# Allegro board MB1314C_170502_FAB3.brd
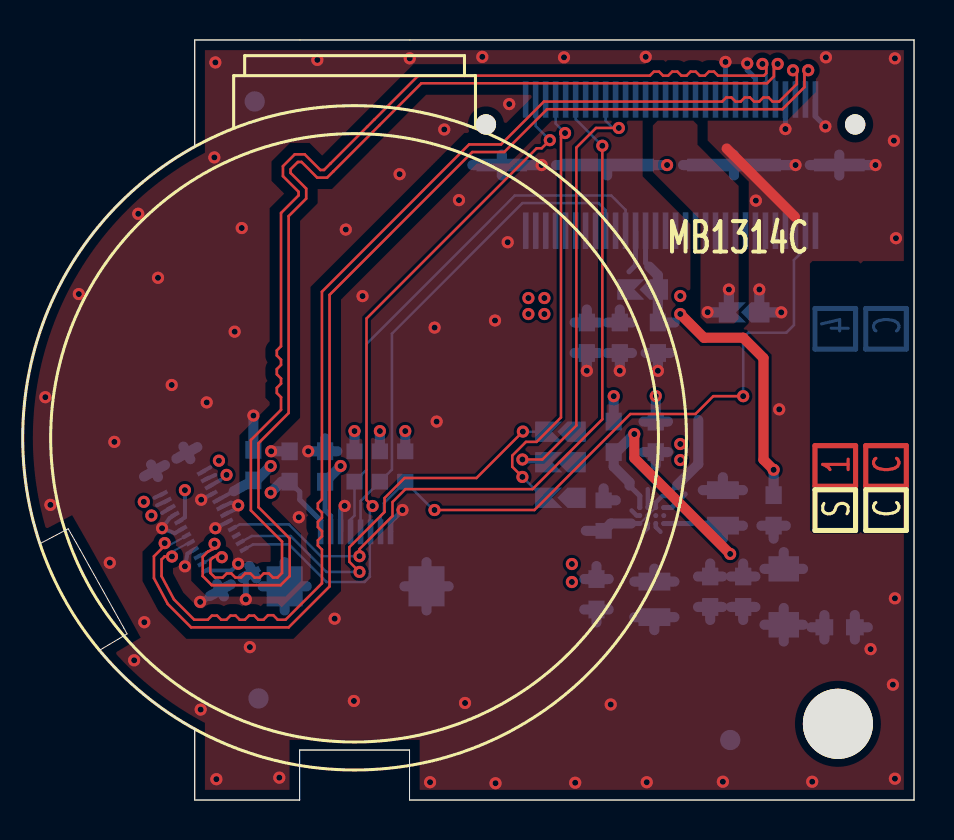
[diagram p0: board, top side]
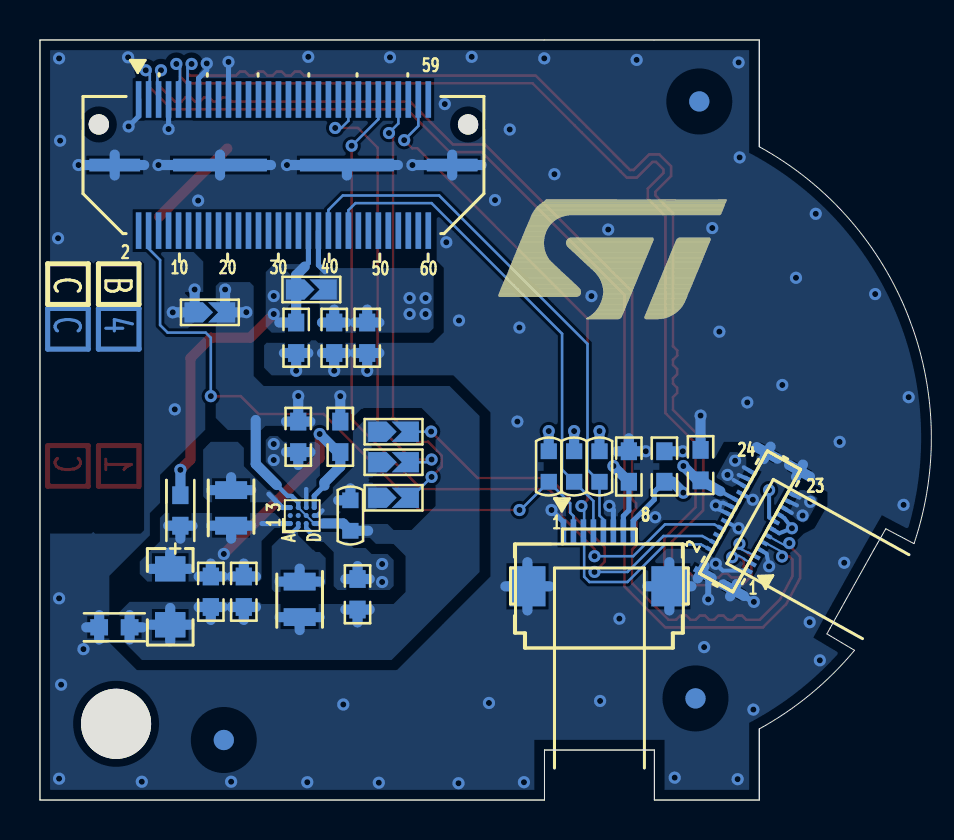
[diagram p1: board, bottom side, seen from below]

Outline 43.75 x 38 mm; copper layers: TOP, L2_GND, L3_VCC, BOTTOM. Coordinates in mm from the lower left corner of the outline.
Outline path: 7.75,32.67 arc(0.27,24.15) 0,12.82 0.02,12.83 1.41,13.56 1.99,12.55 4.21,8.59 4.36,8.31 2.98,7.49 arc(5.18,5.3) 7.75,3.55 ; 7.75,32.67 7.75,38 ; 7.75,32.67 7.75,38 ; 7.75,38 13.01,38 ; 7.75,38 13.01,38 ; 13.01,38 18.51,38 ; 13.01,38 18.51,38 ; 7.75,3.55 7.75,0 ; 7.75,3.55 7.75,0 ; 7.75,0 13,0 ; 7.75,0 13,0 ; 13,0 13,2.5 ; 13,0 13,2.5 ; 13,2.5 18.5,2.5 ; 13,2.5 18.5,2.5 ; 18.5,2.5 18.5,0 ; 18.5,2.5 18.5,0 ; 18.51,38 43.75,38 ; 18.51,38 43.75,38 ; 18.5,0 43.75,0 ; 18.5,0 43.75,0 ; 43.75,0 43.75,38 ; 43.75,0 43.75,38

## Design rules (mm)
net group DIFFPAIR1: nets HSSI_D0_N HSSI_D0_P

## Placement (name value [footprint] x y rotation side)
C1  100nF  [0603C]  30.92 23.11 270 bottom
C2  100nF  [0603C]  29.02 23.11 270 bottom
C3  100nF  [0603C]  27.37 23.11 90 bottom
C4  GRM188R61A106KE69D  [0603C]  30.82 18.16 90 bottom
C5  GRM188R61A106KE69D  [0603C]  28.71 18.16 90 bottom
C6  100nF  [0603C]  10.68 16.75 270 bottom
C7  100nF  [0603C]  14.27 16.68 270 bottom
C8  100nF  [0603C]  12.49 16.68 270 bottom
C9  GRM188R61A106KE69D  [0603C]  33.54 10.41 270 bottom
C10  GRM188R61A106KE69D  [0603C]  27.85 10.29 270 bottom
C11  10uF  [TAN-A]  37.23 10.16 90 bottom
C12  100nF  [0603C]  35.19 10.41 270 bottom
CN1  QTH-030-02-F-D-A-K-TR  [QTH-030-02-F-D-A]  31.56 31.75 180 bottom
CN2  BM20B(0.8)-24DS-0.4V(51)  [HRS_BM20B-24DS-0R4V]  8.19 13.93 119 bottom
CN3  FH19C-8S-05SH  [CONN_8SM_FPC05008-09200]  17.55 13.41 180 bottom
L1  DFE201610E-4R7M=P2  [0806L]  34.18 14.61 270 bottom
L2  DFE201610E-4R7M=P2  [0806L]  30.75 10.03 90 bottom
L3  BEAD(FCM1608KF-601T03)  [0603L]  36.72 14.48 270 bottom
L4  BEAD(FCM1608KF-601T03)  [0603L]  40.02 8.64 180 bottom
NOREF  -  []  175.99 162.03 0 top
NOREF#2  -  []  -3.54 97 0 top
NOREF#3  -  [unnamed#2]  39.94 3.81 0 top
NOREF#4  -  []  7.75 0 0 top
NOREF#5  -  []  369.84 -81.28 0 top
NOREF#6  -  []  43.75 0 90 top
NOREF#7  -  []  -1.25 0 0 top
NOREF#8  -  []  15.75 18.11 0 top
NOREF#9  -  []  7.75 38 0 top
NOREF#10  -  []  165.46 127.75 0 top
NOREF#11  -  []  18.5 0 0 top
NOREF#12  -  []  43.11 16.7 90 top
NOREF#13  -  []  38.81 35.03 0 top
NOREF#14  -  []  43.75 0 90 top
NOREF#15  -  []  0.26 24.12 0 top
NOREF#16  -  []  38.81 35.03 90 top
NOREF#17  -  []  2.81 -24.89 0 top
NOREF#18  -  []  41.29 2.7 0 top
NOREF#19  -  []  39.94 3.81 0 top
NOREF#20  -  []  40.57 16.7 90 top
NOREF#21  Value  []  15.75 18.11 180 top
NOREF#22  -  []  7.75 0 0 top
NOREF#23  -  [unnamed#2]  10.94 5.08 180 bottom
NOREF#24  -  [unnamed#2]  10.75 34.93 180 bottom
NOREF#25  -  [unnamed#2]  34.55 3 180 bottom
R1  4K7  [0603R]  18.28 16.68 270 bottom
R2  [N_A]  [0603R]  17.01 16.68 90 bottom
R3  [N_A]  [0603R]  15.74 16.68 90 bottom
R4  [N_A]  [0603R]  28.21 14.22 90 bottom
SB1  Solder Bridge OFF  [SB_0603]  30.16 25.53 0 bottom
SB2  Solder Bridge OFF  [SB_0603]  35.24 24.38 0 bottom
SB3  Solder Bridge ON  [SB_0603]  26.05 18.41 0 bottom
SB4  Solder Bridge OFF  [SB_0603]  26.05 16.89 0 bottom
SB5  Solder Bridge OFF  [SB_0603]  26.05 15.11 0 bottom
U1  SM3321  [WLCSP12_0R4_1R53X1R74]  30.62 14.22 90 bottom

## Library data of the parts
C1-C10 C12 = 0603C
C11 = TAN-A
CN1 = QTH-030-02-F-D-A
CN2 = HRS_BM20B-24DS-0R4V
CN3 = CONN_8SM_FPC05008-09200
L1 L2 = 0806L
L3 L4 = 0603L
R1-R4 = 0603R
SB1-SB5 = SB_0603
U1 = WLCSP12_0R4_1R53X1R74

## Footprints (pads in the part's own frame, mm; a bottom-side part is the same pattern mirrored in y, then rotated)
0603C
  rect 0.889x0.813 smd: 1(-0.762,0) 2(0.762,0)
0603L
  rect 0.889x0.813 smd: 1(-0.762,0) 2(0.762,0)
0603R
  rect 0.787x0.813 smd: 1(-0.762,0) 2(0.762,0)
0806L
  rect 0.889x1.6 smd: 1(-0.889,0) 2(0.889,0)
CONN_8SM_FPC05008-09200
  rect 0.279x1.245 smd: 1(0,0) 2(0.5,0) 3(1,0) 4(1.5,0) 5(2,0) 6(2.5,0) 7(3,0) 8(3.5,0)
  rect 1.803x2.007 smd: 9(-1.8,-2.725) 10(5.3,-2.725)
HRS_BM20B-24DS-0R4V
  rect 0.203x0.457 smd: 1(-2.2,-1.09) 2(-2.2,1.09) 3(-1.8,-1.09) 4(-1.8,1.09) 5(-1.4,-1.09) 6(-1.4,1.09) 7(-1,-1.09) 8(-1,1.09) 9(-0.6,-1.09) 10(-0.6,1.09) 11(-0.2,-1.09) 12(-0.2,1.09) 13(0.2,-1.09) 14(0.2,1.09) 15(0.6,-1.09) 16(0.6,1.09) 17(1,-1.09) 18(1,1.09) 19(1.4,-1.09) 20(1.4,1.09) 21(1.8,-1.09) 22(1.8,1.09) 23(2.2,-1.09) 24(2.2,1.09)
  rect 0.305x0.787 smd: 25(-3.41,0.925) 26(-3.41,-0.925) 27(3.41,0.925) 28(3.41,-0.925)
QTH-030-02-F-D-A
  round 1.016 hole 1.016 unplated: (-9.24,2.03) (9.24,2.03)
  rect 0.279x1.829 smd: 1(-7.25,3.28) 2(-7.25,-3.28) 3(-6.75,3.28) 4(-6.75,-3.28) 5(-6.25,3.28) 6(-6.25,-3.28) 7(-5.75,3.28) 8(-5.75,-3.28) 9(-5.25,3.28) 10(-5.25,-3.28) 11(-4.75,3.28) 12(-4.75,-3.28) 13(-4.25,3.28) 14(-4.25,-3.28) 15(-3.75,3.28) 16(-3.75,-3.28) 17(-3.25,3.28) 18(-3.25,-3.28) 19(-2.75,3.28) 20(-2.75,-3.28) 21(-2.25,3.28) 22(-2.25,-3.28) 23(-1.75,3.28) 24(-1.75,-3.28) 25(-1.25,3.28) 26(-1.25,-3.28) 27(-0.75,3.28) 28(-0.75,-3.28) 29(-0.25,3.28) 30(-0.25,-3.28) 31(0.25,3.28) 32(0.25,-3.28) 33(0.75,3.28) 34(0.75,-3.28) 35(1.25,3.28) 36(1.25,-3.28) 37(1.75,3.28) 38(1.75,-3.28) 39(2.25,3.28) 40(2.25,-3.28) 41(2.75,3.28) 42(2.75,-3.28) 43(3.25,3.28) 44(3.25,-3.28) 45(3.75,3.28) 46(3.75,-3.28) 47(4.25,3.28) 48(4.25,-3.28) 49(4.75,3.28) 50(4.75,-3.28) 51(5.25,3.28) 52(5.25,-3.28) 53(5.75,3.28) 54(5.75,-3.28) 55(6.25,3.28) 56(6.25,-3.28) 57(6.75,3.28) 58(6.75,-3.28) 59(7.25,3.28) 60(7.25,-3.28)
  rect 2.54x0.635 smd: 61(-8.445,0) 64(8.445,0)
  rect 4.699x0.635 smd: 62(-3.175,0) 63(3.175,0)
SB_0603
  round 0.152 smd: 1(-0.762,0) 2(0.762,0)
TAN-A
  rect 1.27x1.524 smd: 1(1.397,0) 2(-1.397,0)
unnamed#2
  round 3.505 hole 3.505 unplated: (0,0)
WLCSP12_0R4_1R53X1R74
  round 0.254 smd: A1(-0.4,0.6) A2(0,0.6) A3(0.4,0.6) B1(-0.4,0.2) B2(0,0.2) B3(0.4,0.2) C1(-0.4,-0.2) C2(0,-0.2) C3(0.4,-0.2) D1(-0.4,-0.6) D2(0,-0.6) D3(0.4,-0.6)

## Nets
+3V3: C1.1 C6.2 C8.2 CN1.36 CN2.16 CN3.8 L3.1 SB1.2
GND: C1.2 C2.2 C3.1 C6.1 C7.1 C8.1 CN1.1 CN1.7 CN1.13 CN1.19 CN1.61 CN1.62 CN1.63 CN1.64 CN2.1 CN2.7 CN2.10 CN2.12 CN2.13 CN2.14 CN2.17 CN2.18 CN2.25 CN2.26 CN2.27 CN2.28 CN3.1 CN3.6 CN3.9 CN3.10 L4.1 SB2.2
VDD: C2.1 C3.2 C7.2 CN1.38 CN2.15 CN3.7 R1.1 R2.2 R3.2 SB1.1
BLGND: C4.2 C5.2 C9.2 C10.2 C11.2 C12.2 L2.1 L4.2 R4.1 SB2.1 U1.B3 U1.C2 U1.D1
DSI_BL_CTRL: CN1.53 SB5.1
DSI_INT: CN1.4 CN3.2 R1.2
DSI_RST: CN1.57 CN2.2 CN3.3
DSI_TE: CN1.49 CN2.8
ELVDD: C4.1 CN2.20 CN2.22 CN2.24 U1.C3
ELVSS: C10.1 CN2.19 CN2.21 CN2.23 U1.C1
HSSI_CLK_N: CN1.5 CN2.9
HSSI_CLK_P: CN1.3 CN2.11
HSSI_D0_N: CN1.11 CN2.3
HSSI_D0_P: CN1.9 CN2.5
I2C_SCL: CN1.44 CN3.4 R2.1
I2C_SDA: CN1.40 CN3.5 R3.1
NETC5_1: C5.1 C9.1 C11.1 C12.1 L1.2 L3.2 U1.A1 U1.D3
NETL1_1: L1.1 U1.A3
NETL2_2: L2.2 U1.B1
NETR4_2: R4.2 SB3.2 SB4.2 SB5.2 U1.D2
SWIRE: CN2.4 SB3.1
SWIRE_MCU: CN1.43 SB4.1

Pads without a net: CN1 2 6 8 10 12 14 15 16 17 18 20 21 22 23 24 25 26 27 28 29 30 31 32 33 34 35 37 39 41 42 45 46 47 48 50 51 52 54 55 56 58 59 60; CN2 6; U1 A2 B2

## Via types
v1: diameter 0.61, hole 0.305, TOP to BOTTOM, 129 vias

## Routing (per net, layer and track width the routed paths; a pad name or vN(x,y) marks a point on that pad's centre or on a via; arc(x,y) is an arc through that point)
+3V3: length 25.4
  TOP w0.508: v1(32.05,24.3) 33.23,23.11 35.19,23.11 36.21,22.1 36.21,17.02 v1(36.72,16.51)
  BOTTOM w0.2: CN2.16 9.7,15.44
  BOTTOM w0.254: CN3.8 14.05,13.97 13,15.02 13,15.41 C8.2 ; CN1.36 30.31,26.86 30.5,26.67
  BOTTOM w0.508: v1(11.55,15.37) 12.09,15.91 C8.2 ; 30.5,26.67 30.92,26.24 SB1.2 C1.1 31.77,23.88 ; v1(11.55,16.7) 10.83,15.98 C6.2 9.7,15.44 ; L3.1 v1(36.72,16.51)
  vias: v1(32.05,25.2)
GND: length 78.3
  TOP w0.508: 37.79,29.16 34.37,32.58
  BOTTOM w0.2: v1(7.25,11.68) 7.38,12.32 CN2.7 ; CN2.12 9.87,14.58 v1(9.92,14.73) 9.84,14.82 9.56,14.87 CN2.14 ; CN2.10 v1(8.78,13.59) ; CN2.18 v1(8.07,15.01) ; CN2.17 6.49,14.1 v1(6.11,13.59) 6.75,13.34 CN2.13 ; v1(9.92,11.81) 9.58,11.47 CN2.1
  BOTTOM w0.254: CN1.13 35.81,36.09 35.4,36.5 v1(35.4,36.83) ; CN3.6 15.05,14.5 15.26,14.71 v1(15.25,14.71) ; v1(18.15,14.5) 17.55,13.9 17.55,13.41 CN3.1 ; CN1.1 38.81,34.18 v1(39.31,33.68) ; CN1.7 v1(37.31,33.55) ; CN1.19 v1(34.31,36.91)
  BOTTOM w0.3: v1(10.3,10.03) 10.3,11.04 CN2.25 ; 9.03,10.49 v1(8.02,9.91)
  BOTTOM w0.508: 25.83,31.75 CN1.63 ; CN1.63 v1(31.39,31.75) ; CN1.63 28.38,31.23 ; CN1.62 v1(37.82,31.75) ; CN1.62 34.73,31.23 ; CN1.62 32.18,31.75 ; CN1.62 34.73,32.27 ; CN3.9 20.45,10.69 ; CN3.9 18.24,10.69 ; CN3.9 19.35,11.89 ; CN3.9 19.35,9.48 ; L4.1 40.78,9.25 ; L4.1 41.43,8.64 ; L4.1 40.78,8.03 ; 38.53,31.75 CN1.61 ; CN1.61 40,31.23 ; CN1.61 v1(41.82,31.75) ; CN1.61 40,32.27 ; CN2.28 5.91,16.15 ; CN2.28 6.26,16.75 ; CN2.28 5.56,16.77 ; CN2.28 5.21,16.17 ; CN3.10 12.25,11.89 ; CN3.10 12.25,9.48 ; CN3.10 13.35,10.69 ; CN3.10 11.14,10.69 ; 28.41,22.35 C2.2 ; C2.2 v1(29.02,21.46) ; C2.2 29.63,22.35 ; 8.51,10.21 9.03,10.49 ; 9.03,10.49 8.86,10.81 ; 9.03,10.49 9.56,10.78 ; 9.03,10.49 9.21,10.18 ; C7.1 14.88,17.44 ; C7.1 v1(13.43,17.44) ; C7.1 14.27,18.09 ; 10.13,11.1 CN2.25 ; CN2.25 10.83,11.08 ; CN2.25 10.48,11.7 ; C1.2 v1(30.92,21.46) ; C1.2 31.53,22.35 ; C1.2 30.31,22.35 ; 6.83,17.07 CN2.27 ; CN2.27 7.87,17.65 ; CN2.27 7.52,17.05 ; CN2.27 7.18,17.67 ; C3.1 v1(27.37,21.46) ; C3.1 26.76,22.35 ; C3.1 27.98,22.35 ; v1(36,25.53) SB2.2 v1(37.1,24.38) ; C8.1 v1(11.57,17.44) ; C6.1 v1(10.68,19.22) ; 23.11,31.23 CN1.64 ; CN1.64 23.11,32.27 ; CN1.64 v1(25.11,31.75) ; CN1.64 21.64,31.75
  vias: v1(0.27,20.14) v1(0.52,14.76) v1(1.95,25.3) v1(3.5,11.86) v1(3.72,17.91) v1(4.71,6.99) v1(4.92,29.31) v1(5.22,8.89) v1(5.91,26.11) v1(6.59,20.75) v1(8.04,4.52) v1(8.35,19.88) v1(8.78,36.88) v1(8.73,32.13) v1(8.83,1.04) v1(9.74,23.42) v1(10.1,28.6) v1(10.51,7.65) v1(11.98,1.12) v1(12.96,14.14) v1(13.88,37.01) v1(14.75,9.07) v1(15.31,28.52) v1(15.71,4.95) v1(16.14,25.2) v1(18,31.29) v1(18.51,37.08) v1(19.52,0.89) v1(19.75,23.62) v1(19.85,18.92) v1(20.23,33.53) v1(20.97,30) v1(21.28,4.85) v1(22.14,37.16) v1(22.77,23.98) v1(22.8,0.84) v1(23.49,34.8) v1(23.41,27.89) v1(26.23,37.13) v1(26.79,0.86) v1(28.57,4.78) v1(30.32,37.16) v1(30.37,0.89) v1(34.18,0.91) v1(35.83,29.97) v1(37,19.53) v1(38.65,0.91) v1(39.33,37.13) v1(41.57,7.54) v1(42.69,5.77) v1(42.79,37.08) v1(42.74,32.97) v1(42.79,10.08) v1(42.79,1.07) v1(42.84,28.09)
VDD: length 14.4
  BOTTOM w0.2: CN2.15 7.25,14.14 v1(7.25,15.49)
  BOTTOM w0.254: CN1.38 29.81,26.75 29.48,26.42 ; C7.2 14.27,14.48 14.55,14.2 CN3.7
  BOTTOM w0.508: C2.1 29.02,24.52 ; C2.1 28.41,23.88 ; C2.1 29.63,23.88 ; C3.2 27.98,23.88 ; C3.2 27.37,24.52 ; C3.2 26.76,23.88 ; R2.2 v1(17.01,18.45) ; R1.1 v1(18.28,18.45) ; R3.2 v1(15.74,18.45) ; v1(15.05,16.7) 15.05,16.69 C7.2
  vias: v1(24.45,25.1) v1(24.45,24.3) v1(25.25,25.1) v1(25.25,24.3)
BLGND: length 29.1
  BOTTOM w0.102: U1.B3 U1.C2 U1.D1
  BOTTOM w0.22: 31.9,15.75 31.35,15.2 31.15,15.2 30.82,14.87 U1.B3
  BOTTOM w0.254: 29.58,13.83 29.9,13.83 29.89,13.82 U1.D1
  BOTTOM w0.508: C10.2 28.46,9.53 ; C10.2 27.24,9.53 ; C10.2 27.85,8.88 ; 38.61,8.64 L4.2 ; L4.2 39.26,9.25 ; L4.2 39.26,8.03 ; 34.58,9.65 C12.2 ; C12.2 35.19,9 ; C12.2 35.8,9.65 ; 29.75,9.14 L2.1 ; L2.1 31.75,9.14 ; L2.1 30.75,8.5 ; C11.2 38.19,8.76 ; C11.2 36.26,8.76 ; C11.2 37.23,9.6 ; C11.2 37.23,7.92 ; C9.2 34.15,9.65 ; C9.2 33.54,9 ; C9.2 32.93,9.65 ; v1(34.48,25.53) SB2.1 33.42,24.38 v1(33.42,24.39) ; 27.32,13.46 R4.1 28.57,13.83 29.58,13.83 ; C5.2 v1(28.71,20.19) ; 32.95,19 32.95,16.8 31.9,15.75 ; 30.21,18.92 C4.2 ; C4.2 v1(30.82,20.2) ; C4.2 31.43,18.92
DSI_BL_CTRL: length 22.3
  TOP w0.127: v1(24.15,16.15) 23.64,16.66 23.64,17.22 24.32,17.91 24.85,17.91 26.08,19.13 26.08,33.15 v1(26.28,33.35)
  BOTTOM w0.127: CN1.53 25.81,33.83 26.28,33.36 v1(26.28,33.35) ; v1(24.15,16.15) 25.19,15.11 SB5.1
DSI_INT: length 33.6
  TOP w0.127: v1(19.75,14.5) 24.75,14.5 29.55,19.3 32.8,19.3 33.7,20.19 v1(35.19,20.19)
  BOTTOM w0.127: v1(35.19,20.19) 35.19,23.11 35.45,23.37 37.35,23.37 37.73,23.75 37.73,27 38.31,27.58 CN1.4 ; v1(19.75,14.5) 19.7,14.5 R1.2 17.21,14.84 17.21,14.36 17.05,14.2 CN3.2
DSI_RST: length 35.6
  TOP w0.127: v1(25.52,32.99) 25.11,32.59 24.86,32.59 16.34,24.08 16.34,15 v1(16.65,14.7)
  BOTTOM w0.127: v1(25.52,32.99) 24.81,33.7 CN1.57 ; CN2.2 10.67,12.78 12.47,12.78 14.35,10.9 16.25,10.9 16.51,11.16 16.51,13.45 ; v1(16.65,14.7) 16.51,14.56 16.51,13.45 ; 16.51,13.45 CN3.3
DSI_TE: length 39.2
  TOP w0.127: v1(28.15,32.72) 28.15,19.04 24.65,15.54 18.29,15.54 17.65,14.9 17.65,14.2 15.99,12.55 v1(15.99,12.19)
  BOTTOM w0.127: v1(28.15,32.72) 28.09,32.77 28.08,32.77 26.81,34.04 CN1.49 ; v1(15.99,12.19) 14.05,12.19 12.46,13.78 10,13.78 CN2.8
ELVDD: length 4.5
  BOTTOM w0.2: CN2.20 9.03,16 ; CN2.22 8.78,16.26 ; CN2.24 8.52,16.64
  BOTTOM w0.22: 30.42,15.55 U1.C3
  BOTTOM w0.508: 30.21,17.4 C4.1 ; C4.1 31.43,17.4 ; C4.1 30.82,16.75
  vias: v1(8.96,16.97) v1(9.34,16.26) v1(32.05,17.8) v1(32.05,17)
ELVSS: length 3.9
  BOTTOM w0.2: CN2.19 6.11,14.35 ; CN2.21 5.86,14.73 ; CN2.23 5.73,15.11
  BOTTOM w0.22: 30.25,13.4 30.25,13.43 30.42,13.6 U1.C1
  BOTTOM w0.508: 27.85,11.05 28.46,11.05 ; 27.85,11.05 27.24,11.05 ; 27.85,11.05 27.85,11.7
  vias: v1(5.2,14.91) v1(5.58,14.22) v1(26.62,11.8) v1(26.62,10.9)
HSSI_CLK_N: length 59.2
  TOP w0.13: v1(37.69,36.49) 37.88,36.3 37.88,35.8 37,34.92 36.67,34.92 36.46,35.13 36.2,35.13 36,34.92 35.74,34.92 35.53,35.13 35.27,35.13 35.07,34.92 34.81,34.92 34.6,35.13 34.35,35.13 34.14,34.92 25.22,34.92 23.08,32.78 21.48,32.78 14.11,25.42 14.11,15.03 13.91,14.83 13.91,14.57 14.11,14.37 14.11,14.11 13.91,13.91 13.91,13.65 14.11,13.45 14.11,13.19 13.91,12.98 13.91,12.72 14.11,12.52 14.11,10.84 12.29,9.01 11.9,9.01 11.68,9.24 11.41,9.24 11.19,9.01 10.93,9.01 10.72,9.22 10.46,9.22 10.26,9.01 10,9.01 9.79,9.22 9.53,9.22 9.33,9.01 9.07,9.01 8.86,9.22 8.61,9.22 8.4,9.01 7.72,9.01 6.71,10.03 6.09,11.19 6.09,12.03 6.24,12.18 v1(6.61,12.18)
  BOTTOM w0.102: CN2.9 7.29,12.78 6.69,12.45 v1(6.61,12.18)
  BOTTOM w0.13: v1(37.69,36.49) 37.87,36.31 37.87,35.92 37.81,35.86 CN1.5
HSSI_CLK_P: length 59.2
  TOP w0.13: v1(6.24,12.85) 6.19,12.67 5.71,12.18 5.71,11.09 6.4,9.8 7.56,8.63 12.45,8.63 14.49,10.68 14.49,25.26 21.64,32.4 23.24,32.4 25.38,34.54 37.16,34.54 38.26,35.64 38.26,36.3 v1(38.45,36.49)
  BOTTOM w0.102: v1(6.24,12.85) 6.25,12.82 6.5,12.75 6.93,12.99 CN2.11
  BOTTOM w0.13: v1(38.45,36.49) 38.25,36.29 38.25,35.94 38.31,35.88 CN1.3
HSSI_D0_N: length 59.4
  TOP w0.13: v1(9.1,12.14) 8.84,12.22 8.64,12.11 8.53,11.99 8.53,11.35 8.76,11.12 9.14,11.12 9.34,11.33 9.57,11.33 9.78,11.12 10.07,11.12 10.27,11.33 10.53,11.33 10.73,11.12 10.99,11.12 11.2,11.33 11.46,11.33 11.66,11.12 11.89,11.12 12.11,11.35 12.11,12.92 10.56,14.48 10.56,18 12.06,19.51 12.06,20.14 11.86,20.35 11.86,20.61 12.06,20.82 12.06,21.08 11.86,21.29 11.86,21.55 12.06,21.75 12.06,22.01 11.86,22.22 11.86,22.48 12.06,22.69 12.06,29.35 12.94,30.23 12.94,30.41 12.16,31.2 12.16,31.7 12.75,32.28 13.25,32.28 14.03,31.5 14.22,31.5 14.53,31.81 16.37,33.66 16.73,34.02 18.93,36.22 30.53,36.22 30.73,36.42 30.98,36.42 31.18,36.22 31.44,36.22 31.64,36.42 31.9,36.42 32.1,36.22 32.36,36.22 32.56,36.42 32.82,36.42 33.02,36.22 33.28,36.22 33.48,36.42 33.74,36.42 33.94,36.22 36.23,36.22 36.35,36.34 36.35,36.61 v1(36.16,36.81)
  BOTTOM w0.102: CN2.3 8.49,12.03 8.5,12.06 8.78,12.22 v1(9.1,12.14)
  BOTTOM w0.13: v1(36.16,36.81) 36.36,36.6 36.36,35.96 36.31,35.91 CN1.11
HSSI_D0_P: length 59.4
  TOP w0.13: v1(36.92,36.81) 36.73,36.61 36.73,36.18 36.39,35.84 19.09,35.84 17,33.75 16.64,33.39 14.68,31.43 14.37,31.12 13.87,31.12 13.09,31.9 12.91,31.9 12.54,31.54 12.54,31.35 13.32,30.57 13.32,30.07 12.45,29.19 12.45,19.35 10.94,17.84 10.94,14.64 12.5,13.08 12.5,11.19 12.04,10.74 8.6,10.74 8.15,11.2 8.15,12.16 8.4,12.42 8.41,12.42 8.66,12.55 v1(8.74,12.81)
  BOTTOM w0.102: v1(8.74,12.81) 8.66,12.56 8.61,12.53 8.33,12.37 8.3,12.38 7.92,12.17
  BOTTOM w0.13: v1(36.92,36.81) 36.74,36.62 36.74,35.96 36.81,35.89 CN1.9
I2C_SCL: length 25.1
  BOTTOM w0.127: CN3.4 16.05,14.95 R2.1 17.61,16.52 17.61,23.31 24.15,29.84 27.96,29.84 28.31,29.49 CN1.44
I2C_SDA: length 27.1
  BOTTOM w0.127: CN1.40 29.31,29.51 28.59,30.23 23.76,30.23 16.34,22.81 16.34,16.52 R3.1 15.74,14.22 15.55,14.03 CN3.5
NETC5_1: length 25.1
  TOP w0.508: v1(34.54,12.3) 29.75,17.1 v1(29.75,18.3)
  BOTTOM w0.254: U1.A1 32.64,13.82 ; U1.D3 30.02,15.21 29.51,15.72
  BOTTOM w0.508: C9.1 33.54,11.82 ; C9.1 34.15,11.18 ; C9.1 32.93,11.18 ; 36.11,13.72 L3.2 ; L3.2 36.72,13.07 ; L3.2 37.33,13.72 ; C11.1 37.23,12.4 ; C11.1 36.26,11.56 ; C11.1 38.19,11.56 ; C12.1 35.19,11.82 ; C12.1 34.58,11.18 ; C12.1 35.8,11.18 ; 34.18,13.07 L1.2 ; L1.2 33.17,13.72 ; L1.2 35.18,13.72 ; v1(29.75,18.3) 28.84,17.4 C5.1 28.71,16.67 29.51,15.88 29.51,15.72
NETL1_1: length 4
  BOTTOM w0.254: U1.A3 31.62,14.62 32.29,15.3
  BOTTOM w0.508: L1.1 34.18,16.14 ; L1.1 35.18,15.49 ; L1.1 33.17,15.49
NETL2_2: length 3.2
  BOTTOM w0.22: U1.B1 30.82,13.65 31.06,13.41
  BOTTOM w0.508: L2.2 31.75,10.92 ; L2.2 30.75,11.57 ; L2.2 29.75,10.92
NETR4_2: length 1.7
  BOTTOM w0.22: 29.61,14.48 29.86,14.22 U1.D2
  BOTTOM w0.508: 28.82,14.99 R4.2 28.21,15.58
SWIRE: length 20.9
  TOP w0.127: v1(15.99,11.4) 15.48,11.91 15.48,12.64 17.25,14.4 17.25,15.1 18.25,16.1 21.85,16.1 v1(24.17,18.42)
  BOTTOM w0.127: v1(15.99,11.4) 14.34,11.4 12.55,13.2 10.6,13.2 CN2.4 ; v1(24.17,18.42) 24.18,18.41 SB3.1
SWIRE_MCU: length 22.9
  TOP w0.127: v1(28.97,33.6) 27.83,33.6 26.85,32.62 26.85,18.73 25.14,17.03 v1(24.15,17.03)
  BOTTOM w0.127: SB4.1 24.28,16.89 v1(24.15,17.03) ; CN1.43 28.31,33.96 28.67,33.6 v1(28.97,33.6)

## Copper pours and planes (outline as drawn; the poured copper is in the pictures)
+3V3 on BOTTOM (solid shape): 31.43,25.02 30.51,25.02 30,25.53 30.51,26.04 31.43,26.04
+3V3 on BOTTOM: 30.55,26.8 32.05,26.8 32.45,26.4 32.45,23.67 32.15,23.37 30.5,23.37 30.35,23.52 30.35,26.6
+3V3 on L3_VCC: 13.55,13.75 12.95,14.35 12.23,14.35 11,15.58 11,17.69 11.35,18.05 13.74,18.05 14.09,17.69 14.09,16.29 14.64,15.75 18.75,15.75 25.86,22.86 29.86,22.86 30.5,23.5 30.5,26.42 30.88,26.8 32.29,26.8 32.49,26.59 32.49,19.25 29.24,19.25 23.74,13.75
GND on BOTTOM (solid shape): 36.51,23.88 35.59,23.88 35.08,24.38 35.59,24.89 36.51,24.89
GND on TOP: 8.25,0.51 8.25,3.86 5.85,5.41 3.76,7.36 5.04,8.12 4.65,8.83 2.43,12.8 1.61,14.24 0.3,13.55 0.91,24.38 8.25,32.36 8.25,37.49 43.24,37.49 43.24,0.51 19,0.51 19,3.01 12.49,3.01 12.49,0.51 ; 1 cut-out
GND on BOTTOM: 8.25,0.51 8.25,3.86 5.85,5.41 3.76,7.36 5.04,8.12 4.65,8.83 2.43,12.8 1.61,14.24 0.3,13.55 0.91,24.38 8.25,32.36 8.25,37.49 43.24,37.49 43.24,0.51 19,0.51 19,3.01 12.49,3.01 12.49,0.51 ; 4 cut-outs
GND on L2_GND: 8.25,0.51 8.25,3.86 5.85,5.41 3.76,7.36 5.04,8.12 4.65,8.83 2.43,12.8 1.61,14.24 0.3,13.55 0.91,24.38 8.25,32.36 8.25,37.49 43.24,37.49 43.24,0.51 19,0.51 19,3.01 12.49,3.01 12.49,0.51
VDD on BOTTOM (solid shape): 29.75,25.52 30.25,25.02 28.89,25.02 28.89,26.04 30.26,26.04
VDD on BOTTOM: 29.61,23.37 24.27,23.37 24.05,23.59 24.05,26.4 24.25,26.6 29.55,26.6 29.75,26.4 29.75,23.51
VDD on L3_VCC: 32.7,0.51 32.7,15.59 33.4,16.29 33.4,18.71 33,19.11 33,26.81 32.5,27.3 30.62,27.3 29.99,26.67 29.99,23.75 29.61,23.37 25.65,23.37 18.54,16.25 14.85,16.25 14.6,16.51 14.6,17.91 13.95,18.55 11.14,18.55 10.74,18.15 8.54,18.15 7.79,17.41 7.79,15.05 6.75,15.05 5.35,16.45 -0.27,16.45 1.55,25.71 8.25,32.36 8.25,37.49 43.24,37.49 43.24,0.51
BLGND on BOTTOM (solid shape): 34.83,24.38 35.33,23.88 33.97,23.88 33.97,24.89 35.34,24.89
BLGND on TOP: 30.95,34.01 32.65,34.01 32.91,33.76 32.91,32.77 34.97,30.71 34.97,24.05 34.74,23.83 33.37,23.83 33.06,24.13 33.06,29.01 30.67,31.39 30.67,33.73
BLGND on BOTTOM: 33.25,25.9 34.75,25.9 34.95,25.7 34.95,19.1 34.35,18.5 28.05,18.5 27.85,18.7 27.85,19.3 27.55,19.6 24.65,19.6 23.95,18.9 23.95,14.7 25.15,13.5 26.05,13.5 26.35,13.8 27.95,13.8 28.15,13.6 28.15,13 27.95,12.8 26.05,12.8 25.45,12.2 25.45,10.4 26.05,9.8 32.65,9.8 32.76,9.91 39.26,9.91 39.77,9.4 39.77,8.13 38.64,7 26.15,7 21.75,11.4 21.75,19.2 23.25,20.7 32.55,20.7 33.05,21.2 33.05,25.7
DSI_BL_CTRL on BOTTOM (solid shape): 25.64,15.11 26.14,14.61 24.78,14.61 24.78,15.62 26.15,15.62
ELVDD on BOTTOM: 29.73,17.91 31.55,17.91 31.85,18.2 32.25,18.2 32.45,18 32.45,16.91 30.64,15.1 30.45,15.1 30.24,15.3 30.24,15.37 29.73,15.88
ELVDD on BOTTOM: 9.64,15.99 9.42,15.79 9.1,15.65 8.91,15.75 8.4,16.64 8.4,17.12 8.86,17.4 9.22,17.4 9.92,16.13
ELVDD on L3_VCC: 11.35,10.25 10.45,11.15 8.3,14.97 8.3,17.19 8.75,17.65 10.49,17.65 10.49,15.38 12.03,13.85 12.74,13.85 13.34,13.25 23.95,13.25 29.45,18.75 32.64,18.75 32.89,18.49 32.89,16.51 32.34,15.95 29.44,15.95 23.74,10.25
ELVSS on BOTTOM: 28.85,10.5 26.25,10.5 26.05,10.7 26.05,12 26.35,12.3 27.15,12.3 27.45,12.6 28.05,12.6 28.85,13.4 30.05,13.4 30.25,13.6 30.35,13.6 30.45,13.5 30.45,13.4 29.95,12.9 29.55,12.9 29.05,12.4 29.05,10.7
ELVSS on BOTTOM: 6.09,14.21 5.87,14.01 5.54,13.87 5.35,13.97 4.84,14.86 4.84,15.11 5.48,15.49 5.73,15.49 6.37,14.35
ELVSS on L3_VCC: 8.25,0.51 8.25,3.86 5.85,5.41 3.76,7.36 5.04,8.12 4.65,8.83 2.43,12.8 1.61,14.24 0.3,13.55 0,14.74 -0.21,15.95 5.14,15.95 6.29,14.79 6.29,14.69 6.44,14.55 7.95,14.55 10.04,10.85 11.14,9.75 23.96,9.75 29.66,15.45 32.19,15.45 32.19,0.51 19,0.51 19,3.01 12.49,3.01 12.49,0.51
NETC5_1 on BOTTOM: 37.49,14.35 37.74,14.1 37.74,12.93 38.75,11.92 38.75,11.3 38.37,10.92 32.78,10.92 32.65,11.05 32.65,12.95 32.01,13.6 31.75,13.6 31.51,13.83 31.51,13.87 32,14.35
NETL1_1 on BOTTOM: 31.85,15.1 32.25,15.5 32.35,15.5 33.55,16.7 33.55,17.61 33.85,17.91 35.19,17.91 35.58,17.53 35.58,15.18 35.29,14.89 31.86,14.89 31.85,14.9
NETL2_2 on BOTTOM: 29.45,12.1 29.75,12.4 29.95,12.4 30.75,13.2 30.75,13.5 30.85,13.6 31.05,13.6 31.55,13.1 31.75,13.1 32.15,12.7 32.15,10.54 32.01,10.4 29.85,10.4 29.45,10.8
NETR4_2 on BOTTOM (solid shape): 27.32,17.91 26.4,17.91 25.89,18.41 26.4,18.92 27.32,18.92
NETR4_2 on BOTTOM (solid shape): 27.32,16.38 26.4,16.38 25.89,16.89 26.4,17.4 27.32,17.4
NETR4_2 on BOTTOM (solid shape): 27.32,14.61 26.4,14.61 25.89,15.11 26.4,15.62 27.32,15.62
NETR4_2 on BOTTOM: 27.45,19.05 28.08,18.41 28.08,16.64 29.09,15.63 29.09,15.36 29.73,14.71 29.73,14.1 28.97,14.1 28.59,14.48 26.69,14.48 26.43,14.73 26.43,18.67 26.81,19.05
SWIRE on BOTTOM (solid shape): 25.64,18.41 26.14,17.91 24.78,17.91 24.78,18.92 26.15,18.92
SWIRE_MCU on BOTTOM (solid shape): 25.64,16.89 26.14,16.38 24.78,16.38 24.78,17.4 26.15,17.4

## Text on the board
Ref Des/Silkscreen Bottom: B | C
Ref Des/Silkscreen Top: S | C | MB1314C
DIMENSION: 3.5mm
User.23: 1,4 | 5 | N/A | 55 OHM | +/-10%
User.35: FIGURE | SIZE | 0.3048 | 1.016 | 3.5052 | DRILL CHART: TOP to BOTTOM | ALL UNITS ARE IN MILLIMETERS | TOLERANCE | +0.0762/-0.0762 | +0.0508/-0.0508 | PLATED | NON-PLATED | QTY | 130 | 2 | 1
